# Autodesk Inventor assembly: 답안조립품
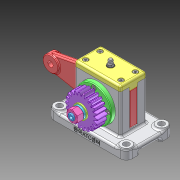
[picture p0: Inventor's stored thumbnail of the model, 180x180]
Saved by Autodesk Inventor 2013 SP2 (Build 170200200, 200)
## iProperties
Created: 2025-04
Part Number: 답안조립품
Document SubType Name: Assembly
Designer: 601
Author: 601
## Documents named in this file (15)
- C:\Users\601\Desktop\750404V1004\답안조립품.iam
- C:\Users\601\Desktop\750404V1004\본체.ipt
- C:\Users\601\Desktop\750404V1004\750404V1004\그리스 니플 M6x0.75.ipt
- C:\Users\601\Desktop\750404V1004\750404V1004\로드.ipt
- C:\Users\601\Desktop\750404V1004\750404V1004\스퍼기어.ipt
- C:\Users\601\Desktop\750404V1004\750404V1004\스프링와셔 M10.ipt
- C:\Users\601\Desktop\750404V1004\750404V1004\실링.ipt
- C:\Users\601\Desktop\750404V1004\750404V1004\앞커버.ipt
- C:\Users\601\Desktop\750404V1004\750404V1004\윗커버.ipt
- C:\Users\601\Desktop\750404V1004\750404V1004\육각 너트 M10.ipt
- C:\Users\601\Desktop\750404V1004\750404V1004\육각 소켓 머리 볼트 M4x10.ipt
- C:\Users\601\Desktop\750404V1004\750404V1004\편심축.ipt
- C:\Users\601\Desktop\750404V1004\750404V1004\평와셔 M10.ipt
- C:\Users\601\Desktop\750404V1004\750404V1004\평행키 4x4x10.ipt
- C:\Users\601\Desktop\750404V1004\750404V1004\플랜지 오일레스 부시.ipt
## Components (3 placed, 2 different names)
1. 그리스 니플 M6x0.75:1
2. 플랜지 오일레스 부시:1
3. 플랜지 오일레스 부시:2
